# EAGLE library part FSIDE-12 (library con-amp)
AMP connector
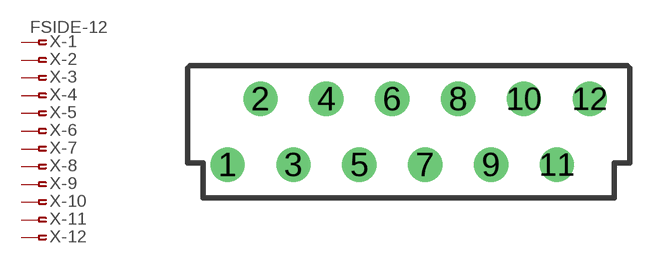
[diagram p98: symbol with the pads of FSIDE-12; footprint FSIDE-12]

Designator prefix X; gates -1=PIN-FV -2=PIN-F -3=PIN-F -4=PIN-F -5=PIN-F -6=PIN-F -7=PIN-F -8=PIN-F -9=PIN-F -10=PIN-F -11=PIN-F -12=PIN-F

## FSIDE-12 (OC_FARNELL: unknown; OC_NEWARK: unknown)  [FSIDE-12]
1  -1:1  pas
2  -2:1  pas
3  -3:1  pas
4  -4:1  pas
5  -5:1  pas
6  -6:1  pas
7  -7:1  pas
8  -8:1  pas
9  -9:1  pas
10  -10:1  pas
11  -11:1  pas
12  -12:1  pas

## Footprint FSIDE-12 (pad centres in mm)
AMP connector
drill 0.813 round: 1 -6.985,-1.27; 2 -5.715,1.27; 3 -4.445,-1.27; 4 -3.175,1.27; 5 -1.905,-1.27; 6 -0.635,1.27; 7 0.635,-1.27; 8 1.905,1.27; 9 3.175,-1.27; 10 4.445,1.27; 11 5.715,-1.27; 12 6.985,1.27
